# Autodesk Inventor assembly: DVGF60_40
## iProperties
Created: 2010-04
Part Number: DVGF60_40
Document SubType Name: Assembly
Designer: TB
Mass: 1063.6 g
Surface Area: 1759.71 cm^2
Volume: 1063.6 cm^3
Density: 1 g/cm^3
Description: KM DVGF 60/40 - 100 mm
Slaglengde: 100.000 mm
Author: TB
